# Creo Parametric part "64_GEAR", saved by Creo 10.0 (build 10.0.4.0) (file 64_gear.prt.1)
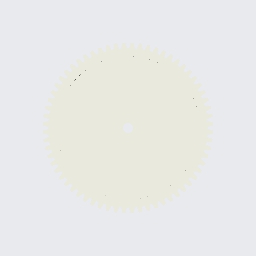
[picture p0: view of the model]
Units: millimeter Kilogram Sec (mmKs); MM, KILOGRAM, SECS

Created from: XX_SOLID_PART_MMKS_NEW_ABS.PRT

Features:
  1. datum plane "RIGHT"
  2. datum plane "TOP"
  3. datum plane "FRONT"
  4. coordinate system
  5. extrusion "Extrude 1"
  6. pattern "Pattern 1"
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
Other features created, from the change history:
  extruded cut "Extrude 2"
  extruded cut "Extrude 2 [2]"
  extruded cut "Extrude 2 [3]"
  extruded cut "Extrude 2 [4]"
  extruded cut "Extrude 2 [5]"
  extruded cut "Extrude 2 [6]"
  extruded cut "Extrude 2 [7]"
  extruded cut "Extrude 2 [8]"
  extruded cut "Extrude 2 [9]"
  extruded cut "Extrude 2 [10]"
  extruded cut "Extrude 2 [11]"
  extruded cut "Extrude 2 [12]"
  extrusion "Extrude 3" (2 times)
  extruded cut "Extrude 4"
  pattern "Pattern 2"
  extruded cut "Extrude 4 [2]"
  extruded cut "Extrude 4 [3]"
  extruded cut "Extrude 4 [4]"
  extruded cut "Extrude 4 [5]"
  extruded cut "Extrude 4 [6]"
  extruded cut "Extrude 4 [7]"
  extruded cut "Extrude 4 [8]"
  extruded cut "Extrude 4 [9]"
  extruded cut "Extrude 4 [10]"
  extruded cut "Extrude 4 [11]"
  extruded cut "Extrude 4 [12]"
  extruded cut "Extrude 4 [13]"
  extruded cut "Extrude 4 [14]"
  extruded cut "Extrude 4 [15]"
  extruded cut "Extrude 4 [16]"
  extruded cut "Extrude 4 [17]"
  extruded cut "Extrude 4 [18]"
  extruded cut "Extrude 4 [19]"
  extruded cut "Extrude 4 [20]"
  extruded cut "Extrude 4 [21]"
  extruded cut "Extrude 4 [22]"
  extruded cut "Extrude 4 [23]"
  extruded cut "Extrude 4 [24]"
  extruded cut "Extrude 4 [25]"
  extruded cut "Extrude 4 [26]"
  extruded cut "Extrude 4 [27]"
  extruded cut "Extrude 4 [28]"
  extruded cut "Extrude 4 [29]"
  extruded cut "Extrude 4 [30]"
  extruded cut "Extrude 4 [31]"
  extruded cut "Extrude 4 [32]"
  extruded cut "Extrude 4 [33]"
  extruded cut "Extrude 4 [34]"
  extruded cut "Extrude 4 [35]"
  extruded cut "Extrude 4 [36]"
  extruded cut "Extrude 4 [37]"
  extruded cut "Extrude 4 [38]"
  extruded cut "Extrude 4 [39]"
  extruded cut "Extrude 4 [40]"
  extruded cut "Extrude 4 [41]"
  extruded cut "Extrude 4 [42]"
  extruded cut "Extrude 4 [43]"
  extruded cut "Extrude 4 [44]"
  extruded cut "Extrude 4 [45]"
  extruded cut "Extrude 4 [46]"
  extruded cut "Extrude 4 [47]"
  extruded cut "Extrude 4 [48]"
  extruded cut "Extrude 4 [49]"
  extruded cut "Extrude 4 [50]"
  extruded cut "Extrude 4 [51]"
  extruded cut "Extrude 4 [52]"
  extruded cut "Extrude 4 [53]"
  extruded cut "Extrude 4 [54]"
  extruded cut "Extrude 4 [55]"
  extruded cut "Extrude 4 [56]"
  extruded cut "Extrude 4 [57]"
  extruded cut "Extrude 4 [58]"
  extruded cut "Extrude 4 [59]"
  extruded cut "Extrude 4 [60]"
  extruded cut "Extrude 4 [61]"
  extruded cut "Extrude 4 [62]"
  extruded cut "Extrude 4 [63]"
  extruded cut "Extrude 4 [64]"
  extrusion "Extrude 5"
  extruded cut "Extrude 6"
  extruded cut "Extrude 7"
  extruded cut "Extrude 8"

Surfaces: 158 plane, 80 cylinder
